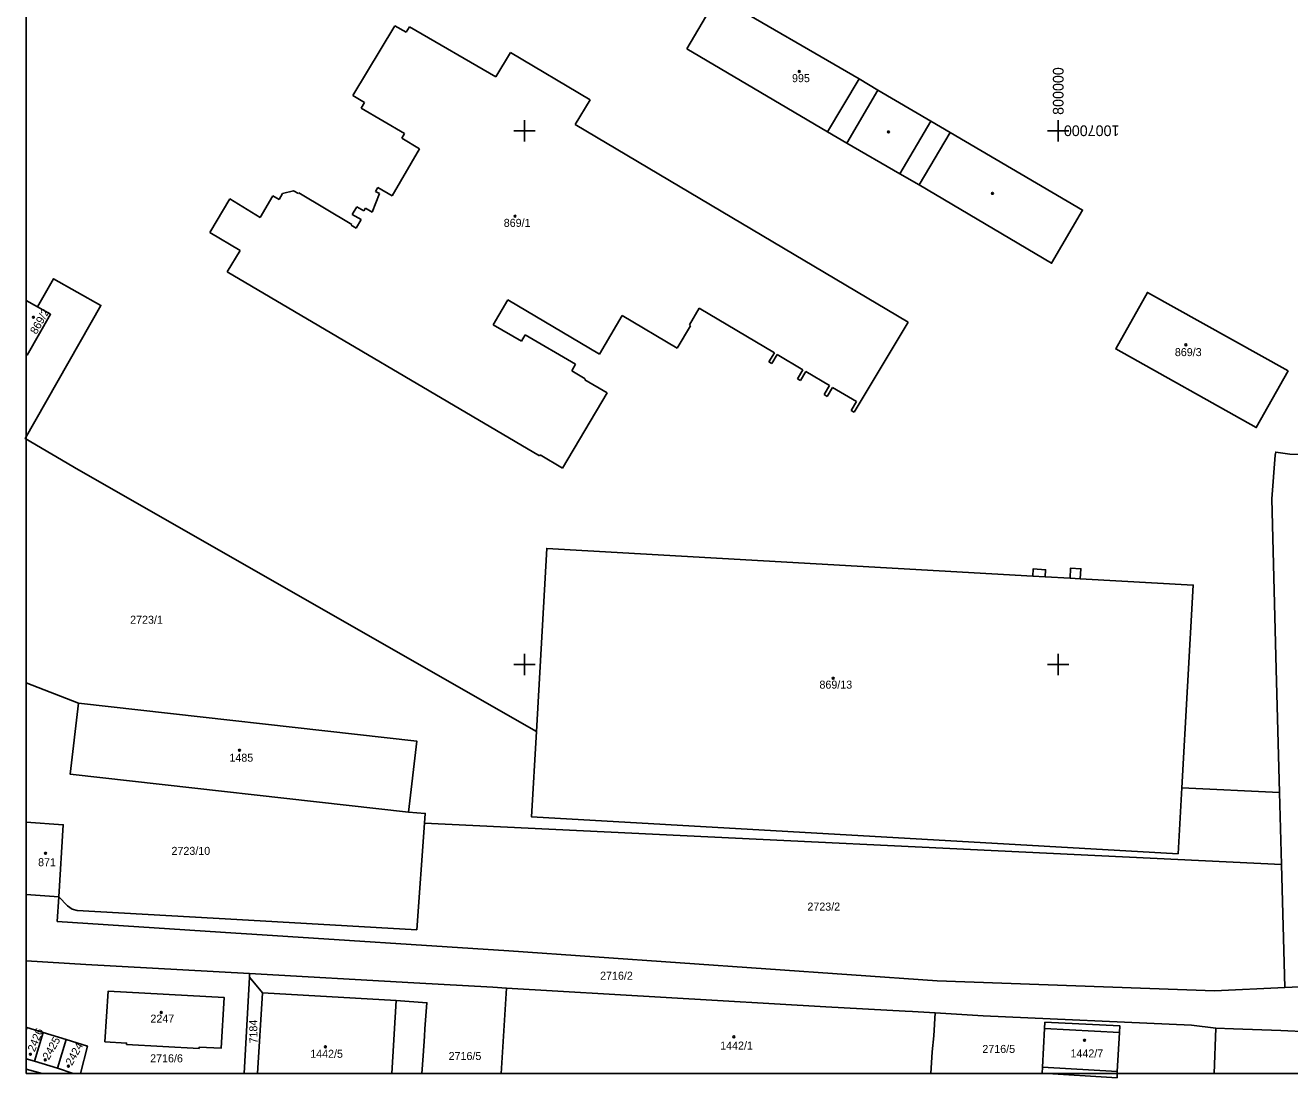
# Model space of a CAD drawing. Extents: x -800194 to -799078, y -1007177 to -1006597.
# Drawn here: x -800193.6 to -799956.6, y -1007177.4 to -1006980.2 of the extents above; entities that cross this region are included whole.
import ezdxf

# ---------------------------------------------------------------- set-up
doc = ezdxf.new("R2010")
doc.units = 0
for name, color, linetype in [('Legenda 1', 7, 'Continuous'), ('Ramove udaje', 7, 'Continuous'), ('Vrstva 55', 7, 'Continuous'), ('Vrstva 56', 7, 'Continuous'), ('Vrstva 57', 7, 'Continuous'), ('Vrstva 59', 7, 'Continuous')]:
    doc.layers.add(name, color=color, linetype=linetype)

msp = doc.modelspace()

# ---------------------------------------------------------------- linework, layer by layer
at = {"layer": 'Legenda 1'}
msp.add_lwpolyline([(-800193.4, -1007176.65), (-799312.4, -1007176.65), (-799312.4, -1006766.65), (-800193.4, -1006766.65)], close=True, dxfattribs=at)
at = {"layer": 'Ramove udaje'}
for p, q in [((-800100, -1006998), (-800100, -1007002)), ((-800000, -1006998), (-800000, -1007002)), ((-800102, -1007000), (-800100, -1007000)), ((-800100, -1007000), (-800098, -1007000)), ((-800002, -1007000), (-800000, -1007000)), ((-800000, -1007000), (-799998, -1007000)), ((-800100, -1007098), (-800100, -1007102)), ((-800000, -1007098), (-800000, -1007102)), ((-800102, -1007100), (-800100, -1007100)), ((-800100, -1007100), (-800098, -1007100)), ((-800002, -1007100), (-800000, -1007100)), ((-800000, -1007100), (-799998, -1007100))]:
    msp.add_line(p, q, dxfattribs=at)
at = {"layer": 'Vrstva 55'}
for p, q in [((-799976.85, -1007123.12), (-799958.55, -1007123.98)), ((-799958.55, -1007123.98), (-799958.18, -1007137.5)), ((-800118.77, -1007129.72), (-799958.18, -1007137.5)), ((-799958.18, -1007137.5), (-799957.55, -1007160.54)), ((-800193.4, -1007143.13), (-800187.33, -1007143.52)), ((-800152.57, -1007176.65), (-800151.6, -1007158.62)), ((-800151.56, -1007157.89), (-800151.6, -1007158.62)), ((-800151.6, -1007158.62), (-800149.16, -1007161.51)), ((-800193.27, -1007168.03), (-800193.4, -1007168.44)), ((-800190.22, -1007168.97), (-800193.27, -1007168.03)), ((-800190.22, -1007168.97), (-800191.87, -1007174.32)), ((-800185.91, -1007170.3), (-800190.22, -1007168.97)), ((-800185.91, -1007170.3), (-800187.57, -1007175.65)), ((-800193.4, -1007173.88), (-800191.87, -1007174.32)), ((-800191.87, -1007174.32), (-800187.57, -1007175.65)), ((-800190.41, -1007176.65), (-800193.4, -1007175.83))]:
    msp.add_line(p, q, dxfattribs=at)
for points in [[(-800069.59, -1006984.65), (-800063.85, -1006974.82), (-800037.33, -1006990.25), (-800033.78, -1006992.42), (-800023.89, -1006998.18), (-800020.27, -1007000.33), (-799995.43, -1007014.87), (-800001.26, -1007024.83), (-800026.05, -1007010.11), (-800029.71, -1007008.06), (-800039.6, -1007002.32), (-800043.23, -1007000.2), (-800069.59, -1006984.65)], [(-799910.85, -1006981.15), (-799907.6, -1006987.58), (-799915.79, -1007002.7), (-799947.77, -1007060.68), (-799956.59, -1007060.62), (-799959.22, -1007060.2), (-799959.32, -1007060.77), (-799959.99, -1007068.95), (-799959.15, -1007100.86), (-799958.55, -1007123.98)], [(-800191.31, -1007032.99), (-800188.29, -1007027.72), (-800179.43, -1007032.73), (-800193.59, -1007057.69), (-800183.59, -1007063.53), (-800097.8, -1007112.58)], [(-799956.91, -1007044.98), (-799962.88, -1007055.62), (-799989.23, -1007040.87), (-799983.28, -1007030.28), (-799956.91, -1007044.98)], [(-800193.4, -1007031.8), (-800191.31, -1007032.99)], [(-800193.4, -1007041.97), (-800193.25, -1007042.05), (-800188.86, -1007034.38), (-800191.31, -1007032.99)], [(-800097.8, -1007112.58), (-800095.87, -1007078.26), (-800004.78, -1007083.43), (-800004.71, -1007082.11), (-800002.37, -1007082.25), (-800002.45, -1007083.56), (-799997.79, -1007083.83), (-799997.69, -1007081.95), (-799995.74, -1007082.06), (-799995.86, -1007083.94), (-799974.69, -1007085.14), (-799976.85, -1007123.12)], [(-800193.4, -1007103.43), (-800183.62, -1007107.27)], [(-800183.62, -1007107.27), (-800185.18, -1007120.54), (-800121.74, -1007127.7)], [(-800121.74, -1007127.7), (-800120.18, -1007114.39), (-800183.62, -1007107.27)], [(-799976.85, -1007123.12), (-799977.55, -1007135.46), (-800098.7, -1007128.56), (-800097.8, -1007112.58)], [(-800121.74, -1007127.7), (-800118.64, -1007127.9), (-800118.77, -1007129.72)], [(-800187.33, -1007143.52), (-800186.47, -1007130.03), (-800193.4, -1007129.55)], [(-800118.77, -1007129.72), (-800120.23, -1007149.7), (-800153.92, -1007147.78), (-800183.84, -1007146.08), (-800184.79, -1007145.86), (-800185.65, -1007145.24), (-800187.33, -1007143.52)], [(-799957.55, -1007160.54), (-799970.7, -1007161.15), (-800022.66, -1007159.29), (-800102.95, -1007153.65), (-800151.15, -1007150.56), (-800154.11, -1007150.37), (-800187.59, -1007148.16), (-800187.33, -1007143.52)], [(-800193.4, -1007155.51), (-800182.23, -1007156.22), (-800151.56, -1007157.89)], [(-800151.56, -1007157.89), (-800120.77, -1007159.66), (-800105.97, -1007160.48), (-800103.43, -1007160.63)], [(-799902.49, -1007157.51), (-799953, -1007168.82), (-799958.28, -1007168.59), (-799967.15, -1007168.25), (-799970.47, -1007168.12)], [(-799957.55, -1007160.54), (-799946.38, -1007160.03), (-799937.79, -1007157.93)], [(-800103.43, -1007160.63), (-800104.39, -1007176.65)], [(-800023.08, -1007165.28), (-800027.33, -1007165.05), (-800028.66, -1007164.97), (-800043.53, -1007164.15), (-800103.43, -1007160.63)], [(-800178.68, -1007170.71), (-800174.59, -1007170.94), (-800174.6, -1007171.19), (-800161.02, -1007171.93), (-800161, -1007171.68), (-800156.91, -1007171.91), (-800156.3, -1007162.43), (-800178.06, -1007161.23), (-800178.68, -1007170.71)], [(-800149.16, -1007161.51), (-800150.05, -1007176.65)], [(-800119.28, -1007176.65), (-800119, -1007173.34), (-800118.76, -1007169.65), (-800118.69, -1007168.26), (-800118.33, -1007163.39), (-800124.09, -1007162.99), (-800149.16, -1007161.51)], [(-800023.85, -1007176.65), (-800023.63, -1007172.6), (-800023.3, -1007169.57), (-800023.08, -1007165.28)], [(-800023.08, -1007165.28), (-800014.06, -1007165.81), (-799975.01, -1007167.61), (-799970.47, -1007168.12)], [(-800193.27, -1007168.03), (-800193.4, -1007167.99)], [(-800002.51, -1007167.02), (-800002.58, -1007168.18), (-800002.95, -1007175.44), (-800003, -1007176.58), (-799988.98, -1007177.43), (-799988.93, -1007176.25), (-799988.52, -1007168.97), (-799988.43, -1007167.73), (-800002.51, -1007167.02)], [(-800183.26, -1007176.65), (-800181.9, -1007171.54), (-800185.91, -1007170.3)], [(-799970.47, -1007168.12), (-799970.77, -1007176.65)], [(-800187.57, -1007175.65), (-800184.62, -1007176.65)]]:
    msp.add_lwpolyline(points, dxfattribs=at)
at = {"layer": 'Vrstva 56'}
for p, q in [((-800124.35, -1006980.32), (-800132.2, -1006993.41)), ((-800122.19, -1006981.56), (-800124.35, -1006980.32)), ((-800121.6, -1006980.54), (-800122.19, -1006981.56)), ((-800105.43, -1006989.93), (-800121.6, -1006980.54)), ((-800102.67, -1006985.33), (-800105.43, -1006989.93)), ((-800087.72, -1006994.21), (-800102.67, -1006985.33)), ((-800037.33, -1006990.25), (-800043.23, -1007000.2)), ((-800039.6, -1007002.32), (-800033.78, -1006992.42)), ((-800132.2, -1006993.41), (-800130.02, -1006994.7)), ((-800130.02, -1006994.7), (-800130.63, -1006995.76)), ((-800090.55, -1006998.86), (-800087.72, -1006994.21)), ((-800130.63, -1006995.76), (-800122.52, -1007000.52)), ((-800028.13, -1007035.85), (-800090.55, -1006998.86)), ((-800029.71, -1007008.06), (-800023.89, -1006998.18)), ((-800123.04, -1007001.41), (-800122.52, -1007000.52)), ((-800123.04, -1007001.41), (-800119.68, -1007003.41)), ((-800026.05, -1007010.11), (-800020.27, -1007000.33)), ((-800119.68, -1007003.41), (-800124.85, -1007012.2)), ((-800143.33, -1007011.23), (-800145.37, -1007011.77)), ((-800142.4, -1007011.79), (-800143.33, -1007011.23)), ((-800142.32, -1007011.66), (-800142.4, -1007011.79)), ((-800132.41, -1007017.55), (-800142.32, -1007011.66)), ((-800127.54, -1007010.61), (-800127.98, -1007011.36)), ((-800127.98, -1007011.36), (-800127.23, -1007011.79)), ((-800124.85, -1007012.2), (-800127.54, -1007010.61)), ((-800155.27, -1007012.78), (-800159.02, -1007019.05)), ((-800149.57, -1007016.23), (-800155.27, -1007012.78)), ((-800149.57, -1007016.23), (-800147.2, -1007012.17)), ((-800146.02, -1007012.87), (-800147.2, -1007012.17)), ((-800145.37, -1007011.77), (-800146.02, -1007012.87)), ((-800128.59, -1007015.24), (-800127.23, -1007011.79)), ((-800132.31, -1007015.7), (-800131.47, -1007014.23)), ((-800130.66, -1007016.65), (-800132.31, -1007015.7)), ((-800131.47, -1007014.23), (-800130.11, -1007015.01)), ((-800130.11, -1007015.01), (-800129.82, -1007014.51)), ((-800129.82, -1007014.51), (-800128.59, -1007015.24)), ((-800132.49, -1007017.68), (-800132.41, -1007017.55)), ((-800131.56, -1007018.23), (-800132.49, -1007017.68)), ((-800131.56, -1007018.23), (-800130.66, -1007016.65)), ((-800159.02, -1007019.05), (-800153.33, -1007022.41)), ((-800153.33, -1007022.41), (-800155.77, -1007026.42)), ((-800097.23, -1007060.91), (-800155.77, -1007026.42)), ((-800103.14, -1007031.67), (-800105.89, -1007036.34)), ((-800103.14, -1007031.67), (-800085.96, -1007041.88)), ((-800085.96, -1007041.88), (-800081.71, -1007034.61)), ((-800071.42, -1007040.72), (-800081.71, -1007034.61)), ((-800067.3, -1007033.22), (-800069.13, -1007036.39)), ((-800067.3, -1007033.22), (-800053.2, -1007041.6)), ((-800105.89, -1007036.34), (-800100.61, -1007039.41)), ((-800071.42, -1007040.72), (-800068.9, -1007036.53)), ((-800069.13, -1007036.39), (-800068.9, -1007036.53)), ((-800028.13, -1007035.85), (-800038.26, -1007052.73)), ((-800100.61, -1007039.41), (-800099.92, -1007038.25)), ((-800099.92, -1007038.25), (-800090.48, -1007043.75)), ((-800053.2, -1007041.6), (-800054.21, -1007043.3)), ((-800053.66, -1007043.63), (-800052.65, -1007041.93)), ((-800052.65, -1007041.93), (-800047.84, -1007044.78)), ((-800091.15, -1007044.99), (-800090.48, -1007043.75)), ((-800054.21, -1007043.3), (-800053.66, -1007043.63)), ((-800047.84, -1007044.78), (-800048.85, -1007046.49)), ((-800091.15, -1007044.99), (-800088.64, -1007046.47)), ((-800088.64, -1007046.47), (-800088.75, -1007046.65)), ((-800084.56, -1007049.14), (-800088.75, -1007046.65)), ((-800048.85, -1007046.49), (-800048.31, -1007046.81)), ((-800048.31, -1007046.81), (-800047.3, -1007045.11)), ((-800047.3, -1007045.11), (-800042.85, -1007047.75)), ((-800092.88, -1007063.2), (-800084.56, -1007049.14)), ((-800042.85, -1007047.75), (-800043.86, -1007049.45)), ((-800043.86, -1007049.45), (-800043.31, -1007049.78)), ((-800043.31, -1007049.78), (-800042.3, -1007048.08)), ((-800042.3, -1007048.08), (-800037.79, -1007050.75)), ((-800037.79, -1007050.75), (-800038.8, -1007052.45)), ((-800038.8, -1007052.45), (-800038.26, -1007052.73)), ((-800097.11, -1007060.7), (-800097.23, -1007060.91)), ((-800097.11, -1007060.7), (-800092.88, -1007063.2)), ((-800002.45, -1007083.56), (-800004.78, -1007083.43)), ((-799997.79, -1007083.83), (-799995.86, -1007083.94)), ((-800124.09, -1007162.99), (-800124.88, -1007176.65)), ((-800002.58, -1007168.18), (-799988.52, -1007168.97)), ((-800002.95, -1007175.44), (-799988.93, -1007176.25))]:
    msp.add_line(p, q, dxfattribs=at)
at = {"layer": 'Vrstva 59'}
for centre in [(-800048.53, -1006988.9), (-800031.82, -1007000.23), (-800012.33, -1007011.74), (-800101.81, -1007016.01), (-800192.07, -1007034.96), (-799976.08, -1007040.1), (-800042.17, -1007102.59), (-800153.45, -1007116.09), (-800189.79, -1007135.38), (-800168.1, -1007165.2), (-800060.79, -1007169.78), (-799995.07, -1007170.42), (-800137.35, -1007171.65), (-800192.64, -1007173.04), (-800189.84, -1007174.1), (-800185.52, -1007175.25)]:
    msp.add_circle(centre, 0.175, dxfattribs=at)

# ---------------------------------------------------------------- texts
at = {"layer": 'Ramove udaje'}
for s, rotation, p in [('    800000', 90, (-799999, -1007000)), ('1007000    ', 180, (-799988.53, -1006999))]:
    msp.add_text(s, height=2, rotation=rotation, dxfattribs=at).set_placement(p)
at = {"layer": 'Vrstva 57'}
for s, p in [('995', (-800049.89, -1006990.9)), ('869/1', (-800103.92, -1007018.01)), ('869/3', (-799978.14, -1007042.23)), ('2723/1', (-800173.94, -1007092.37)), ('869/13', (-800044.75, -1007104.53)), ('1485', (-800155.33, -1007118.22)), ('2723/10', (-800166.19, -1007135.68)), ('871', (-800191.19, -1007137.8)), ('2723/2', (-800047.01, -1007146.12)), ('2716/2', (-800085.86, -1007159.07)), ('2247', (-800170.14, -1007167.11)), ('1442/5', (-800140.19, -1007173.7)), ('2716/5', (-800114.25, -1007174.11)), ('1442/1', (-800063.36, -1007172.16)), ('2716/5', (-800014.22, -1007172.79)), ('1442/7', (-799997.7, -1007173.63)), ('2716/6', (-800170.19, -1007174.55))]:
    msp.add_text(s, height=1.5, dxfattribs=at).set_placement(p)
for s, rotation, p in [('869/2', 60.2504, (-800191.5, -1007038.27)), ('7184', 91, (-800150.06, -1007171.01)), ('2426', 68, (-800191.84, -1007172.68)), ('2425', 60, (-800189.18, -1007174.2)), ('2424', 61, (-800184.85, -1007175.27))]:
    msp.add_text(s, height=1.5, rotation=rotation, dxfattribs=at).set_placement(p)

doc.saveas('drawing.dxf')
